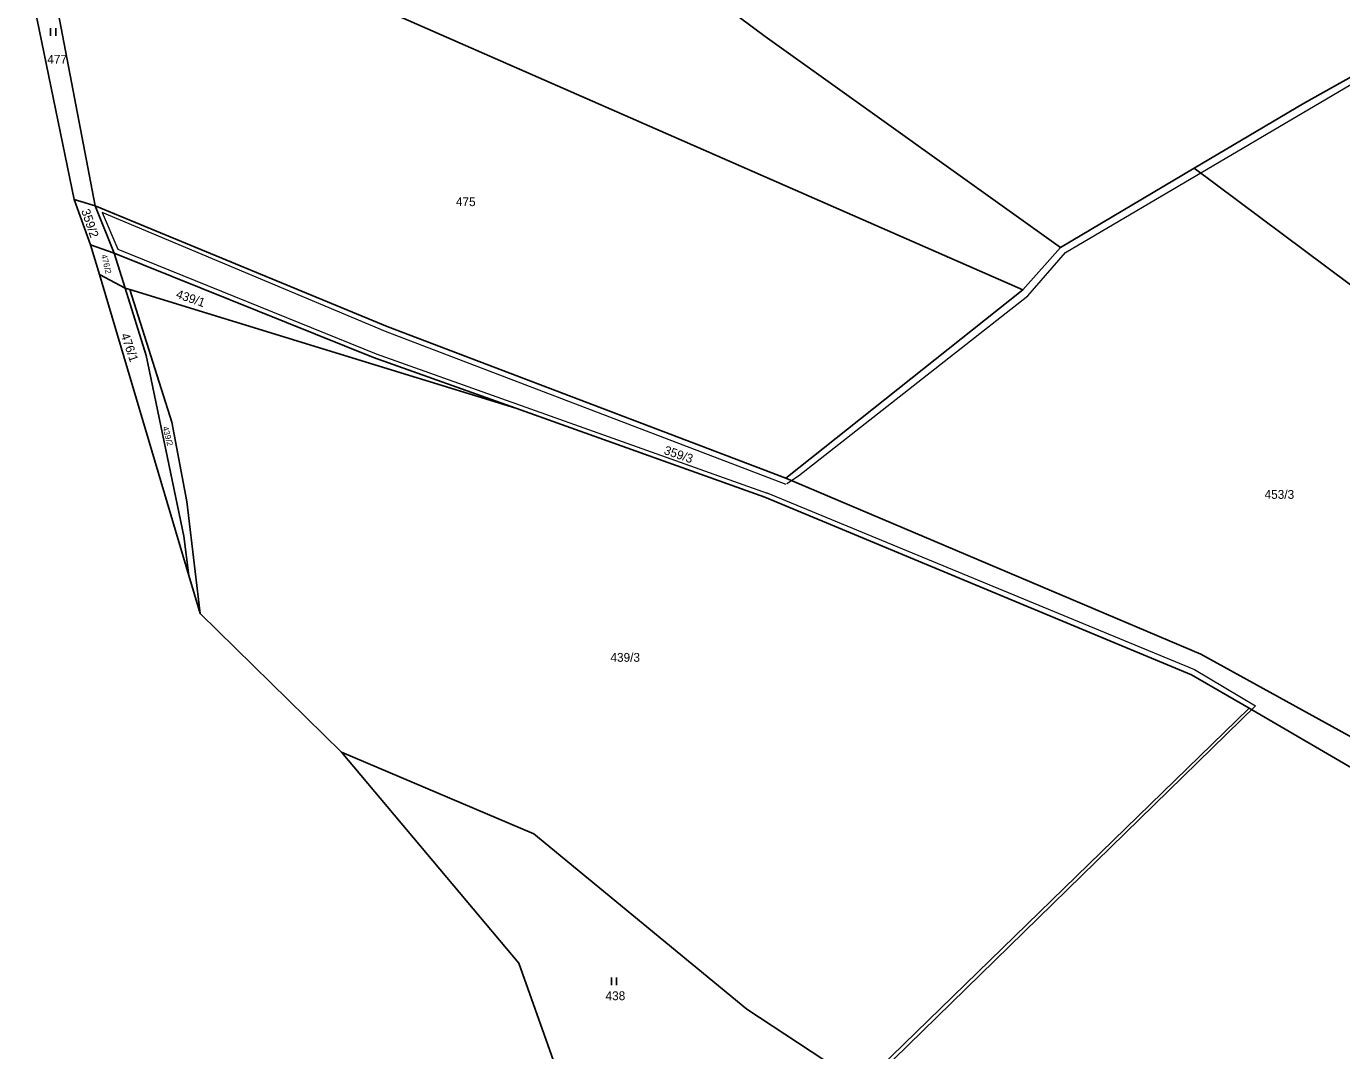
# Model space of a CAD drawing. Extents: x -633485 to -630509, y -1112692 to -1108818.
# Drawn here: x -633411.2 to -633158, y -1111042.2 to -1110845 of the extents above; entities that cross this region are included whole.
import ezdxf
from ezdxf.enums import TextEntityAlignment as Align

# ---------------------------------------------------------------- set-up
doc = ezdxf.new("R2010")
doc.units = 0
doc.header["$LTSCALE"] = 0.68
for name, color, linetype, lineweight in [('1', 7, 'Continuous', 25), ('3', 7, 'Continuous', 25), ('4', 7, 'Continuous', 13)]:
    doc.layers.add(name, color=color, linetype=linetype, lineweight=lineweight)
doc.layers.add('2', color=7, linetype='Continuous')

msp = doc.modelspace()

# ---------------------------------------------------------------- linework, layer by layer
at = {"layer": '1'}
for p, q in [((-633337.57, -1110795.62), (-633268.93, -1110846.94)), ((-633410.85, -1110811.65), (-633397.88, -1110879.52)), ((-633410.85, -1110811.65), (-633219.32, -1110895.7)), ((-633411.15, -1110833.49), (-633401.91, -1110878.32)), ((-633268.93, -1110846.94), (-633212.12, -1110887.58)), ((-633165.33, -1110859.81), (-633153.94, -1110853.48)), ((-633186.36, -1110872.29), (-633165.33, -1110859.81)), ((-633212.12, -1110887.58), (-633186.36, -1110872.29)), ((-633186.36, -1110872.29), (-633150.11, -1110899.39)), ((-633398.77, -1110887.03), (-633401.91, -1110878.32)), ((-633401.91, -1110878.32), (-633397.88, -1110879.52)), ((-633397.88, -1110879.52), (-633394.21, -1110888.62)), ((-633397.88, -1110879.52), (-633341.72, -1110902.78)), ((-633398.77, -1110887.03), (-633394.21, -1110888.62)), ((-633397.08, -1110892.74), (-633398.77, -1110887.03)), ((-633219.32, -1110895.7), (-633212.12, -1110887.58)), ((-633394.21, -1110888.62), (-633344.31, -1110908.74)), ((-633394.21, -1110888.62), (-633392.11, -1110895.39)), ((-633397.08, -1110892.74), (-633392.11, -1110895.39)), ((-633379.87, -1110950.7), (-633397.08, -1110892.74)), ((-633392.11, -1110895.39), (-633391.25, -1110895.67)), ((-633392.11, -1110895.39), (-633388.09, -1110908.33)), ((-633391.25, -1110895.67), (-633316.93, -1110918.52)), ((-633391.25, -1110895.67), (-633383.17, -1110921.19)), ((-633264.94, -1110931.95), (-633219.32, -1110895.7)), ((-633341.72, -1110902.78), (-633264.94, -1110931.95)), ((-633388.09, -1110908.33), (-633380.81, -1110943.13)), ((-633344.31, -1110908.74), (-633316.93, -1110918.52)), ((-633316.93, -1110918.52), (-633268.99, -1110935.64)), ((-633383.17, -1110921.19), (-633380.27, -1110936.44)), ((-633264.94, -1110931.95), (-633185.07, -1110965.84)), ((-633268.99, -1110935.64), (-633186.88, -1110969.84)), ((-633380.27, -1110936.44), (-633377.69, -1110958.05)), ((-633380.81, -1110943.13), (-633379.87, -1110950.7)), ((-633377.69, -1110958.05), (-633379.87, -1110950.7)), ((-633350.51, -1110984.77), (-633377.69, -1110958.05)), ((-633185.07, -1110965.84), (-633126.39, -1110998.31)), ((-633186.88, -1110969.84), (-633175.8, -1110976.29)), ((-633250.28, -1111048.76), (-633175.8, -1110976.29)), ((-633175.8, -1110976.29), (-633116.53, -1111010.8)), ((-633350.51, -1110984.77), (-633313.47, -1111000.45)), ((-633350.51, -1110984.77), (-633316.34, -1111025.35)), ((-633313.47, -1111000.45), (-633272.49, -1111034.22)), ((-633302.17, -1111065.18), (-633316.34, -1111025.35)), ((-633272.49, -1111034.22), (-633255.21, -1111045.57))]:
    msp.add_line(p, q, dxfattribs=at)
at = {"layer": '3'}
for p, q in [((-633406.471, -1110846.81), (-633406.471, -1110845.31)), ((-633405.47, -1110846.81), (-633405.47, -1110845.31)), ((-633298.531, -1111029.63), (-633298.531, -1111028.13)), ((-633297.53, -1111029.63), (-633297.53, -1111028.13))]:
    msp.add_line(p, q, dxfattribs=at)
at = {"layer": '4'}
for points in [[(-633264.76, -1110933.01), (-633262.54, -1110931.54), (-633218.37, -1110896.89), (-633211.16, -1110888.52), (-633154.04, -1110854.86), (-633111.49, -1110867.19), (-633071.81, -1110884.56), (-633030.19, -1110923.4), (-633008.34, -1110955.03), (-632977.94, -1110984.23), (-632970.09, -1110978.65), (-632960.1, -1110988.88), (-632941.26, -1110955.16), (-632931.04, -1110945.63), (-632917.35, -1110915.45), (-632899.91, -1110893.13), (-632857.6, -1110908.01), (-632855.51, -1110913.36), (-632819.47, -1110984.06), (-632805.86, -1111000.27), (-632807.72, -1111003.3), (-632796.56, -1111011.2), (-632797.72, -1111012.6), (-632759.66, -1111042.52)], [(-633264.92, -1110933.18), (-633341.99, -1110903.76), (-633396.56, -1110880.8), (-633393.54, -1110887.89), (-633343.79, -1110908.01), (-633268.53, -1110934.84)], [(-633268.77, -1110934.72), (-633186.32, -1110968.85), (-633174.58, -1110975.83)], [(-633162, -1111176.14), (-633227.1, -1111081.48), (-633250.97, -1111050.06), (-633249.81, -1111049.36), (-633174.56, -1110975.81)]]:
    msp.add_lwpolyline(points, dxfattribs=at)

# ---------------------------------------------------------------- texts
at = {"layer": '2'}
for s, p in [('477', (-633407.11, -1110852.155)), ('475', (-633328.46, -1110879.585)), ('453/3', (-633172.81, -1110935.955)), ('439/3', (-633298.72, -1110967.335)), ('438', (-633299.66, -1111032.505))]:
    msp.add_text(s, height=1.7, dxfattribs=at).set_placement(p)
for s, height, rotation, p in [('359/2', 1.7, 289, (-633400.611, -1110880.468)), ('476/2', 1.139, 284, (-633396.766, -1110889.018)), ('439/1', 1.7, 341, (-633382.478, -1110897.201)), ('476/1', 1.7, 289, (-633393.001, -1110904.378)), ('359/3', 1.7, 341, (-633288.558, -1110927.281))]:
    msp.add_text(s, height=height, rotation=rotation, dxfattribs=at).set_placement(p)
msp.add_text('439/2', height=1.139, rotation=285, dxfattribs=at).set_placement((-633384.4641, -1110924.0086), align=Align.CENTER)

doc.saveas('drawing.dxf')
